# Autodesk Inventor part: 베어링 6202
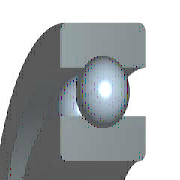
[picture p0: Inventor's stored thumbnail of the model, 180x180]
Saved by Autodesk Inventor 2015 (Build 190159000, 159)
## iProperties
IsCustomPart: 1
Created: 2015-12
Part Number: 베어링 6202
Material: 강철, 연강
Description: 깊은 그루브 볼 베어링
Document SubType Name: Modeling
Standard: KS B 2023
Designer: mdu
Standards Organization: KS
Language: ko-KR
Size Designation: 6202 - 15 x 35 x 11
Categories: <MemberInstance><Categories><Category DisplayName="샤프트 부품" InternalName="7f7aeb1f-a693-4053-b835-cee3144e0d98" Mnemonic="SHFT"><Category DisplayName="베어링" Inter
Density: 7.86 g/cm^3
Mass: 45.8724 g
Surface Area: 51.5584 cm^2
Volume: 5.83618 cm^3
Appearance: 노란색
Author: mdu
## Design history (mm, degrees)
sketch "스케치" dims "d0" = 5.2 (= -0.26 x WD + 0.26 x BD)
  geometry: L1 (2.9, 12.5)-(8.1, 12.5); L2 (5.5, 12.5)-(5.5, 9.9); L3 (5.5, 12.5)-(5.5, 15.1); L4 (3.568, 10.76)-(0, 10.76); L5 (0, 7.5)-(11, 7.5); L6 (3.568, 14.24)-(0, 14.24); L7 (0, 17.5)-(11, 17.5); L8 (11, 7.5)-(11, 10.76); L9 (7.432, 10.76)-(11, 10.76); L10 (7.432, 14.24)-(11, 14.24); L11 (11, 17.5)-(11, 14.24); L12 (-1.4, 0)-(8.4, 0) reference; L13 (0, -0.3)-(0, 5.3) reference
  constraints: 22 end point, 4 point on line, 2 collinear, 2 perpendicular, 2 symmetric about line, 1 midpoint, 1 parallel, 14 other
  dimensions: "d9" = 15 diameter of L5 L12 (= WD); "d11" = 35 diameter of L7 L12 (= BD); "d12" = 11 distance between parallel lines of L8 L13 (= KB); "d13" = 21.52 diameter of L9 L12 (= 0.326 x BD + 0.674 x WD)
revolve "본체" stored, may be unused: angle "d6" = 90 deg
revolve "볼" stored, may be unused: angle "d7" = 90 deg
pattern_circular "IDS_ARRAYBALL[SIMPL:T]" dims angle "d3" = 360 deg
body "Solid1"
fillet "모깎기1" dims "d1" = 0.6 (= KRS)
other parameters: "WD" = 15 [user parameter; used in 5 equation terms], "BD" = 35 [user parameter; used in 5 equation terms], "KB" = 11 [user parameter; used in 1 equation term], "KRS" = 0.6 [user parameter; used in 1 equation term], "d4" = 0, "d5" = 0, "d8" = 0, "d14" = 0, "d15" = 0, "BBA" = 0 [user parameter], "BC0" = 3750000 [user parameter], "BC" = 7800000 [user parameter], "BR" = 17.5 (= 0.5 x BD) [user parameter], "WR" = 7.5 (= 0.5 x WD) [user parameter]
